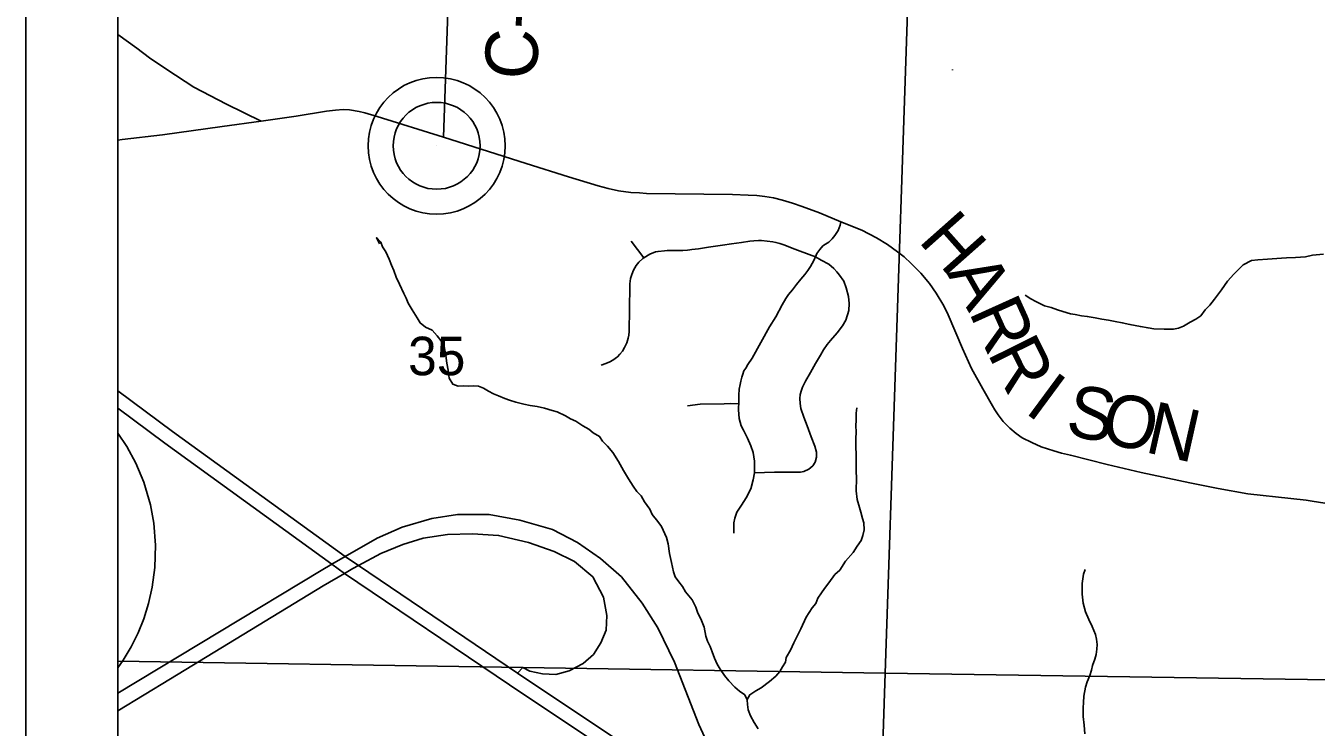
# Model space of a CAD drawing. Extents: x 0 to 34, y 0 to 22.
# Drawn here: x 2 to 3.401, y 17.753 to 18.515 of the extents above; entities that cross this region are included whole.
import ezdxf

# ---------------------------------------------------------------- set-up
doc = ezdxf.new("R2010")
doc.units = 0
for name, color, linetype in [('Default', 7, 'Continuous'), ('GM_X_County_Road', 7, 'Continuous'), ('GM_X_County_Road_Text', 7, 'Continuous'), ('GM_X_Interchange_Ramps', 7, 'Continuous'), ('GM_X_Interstate_Route', 7, 'Continuous'), ('GM_X_Minor_River', 7, 'Continuous'), ('GM_X_Section', 7, 'Continuous'), ('GM_X_Section_Text', 7, 'Continuous'), ('GM_X_State_Route', 7, 'Continuous'), ('GM_X_Township_Road', 7, 'Continuous'), ('GM_X_Unincorporated', 7, 'Continuous'), ('GM_X_Unincorporated_Location', 7, 'Continuous'), ('GM_X_US_Route', 7, 'Continuous'), ('SH_Data', 7, 'Continuous')]:
    doc.layers.add(name, color=color, linetype=linetype)

msp = doc.modelspace()

# ---------------------------------------------------------------- linework, layer by layer
at = {"layer": 'Default'}
for points in [[(2.1, 18.8179), (2.1, 17.8244), (2.9334, 17.8114), (2.9671, 18.8096)], [(2.1, 17.8244), (2.1, 16.8301), (2.9007, 16.8204), (2.9334, 17.8114)]]:
    msp.add_lwpolyline(points, close=True, dxfattribs=at)
at = {"layer": 'GM_X_County_Road'}
for points in [[(2.4536, 18.3939), (2.4734, 18.9711), (2.4789, 19.2126), (2.4779, 19.2343), (2.4729, 19.258), (2.466, 19.2847), (2.4564, 19.3082), (2.4379, 19.3402), (2.4089, 19.3759), (2.4042, 19.3829), (2.4024, 19.3879), (2.4033, 19.3939), (2.5108, 19.6061), (2.522, 19.6255), (2.5381, 19.646), (2.5504, 19.6643), (2.5583, 19.6763), (2.5688, 19.6992), (2.5863, 19.7508)], [(2.1, 18.5055), (2.1205, 18.4907), (2.1344, 18.4804), (2.1533, 18.4675), (2.1824, 18.4485), (2.218, 18.4299), (2.2556, 18.4113)], [(2.1, 18.3907), (2.1045, 18.3913), (2.1483, 18.3966), (2.2132, 18.4055), (2.2556, 18.4113), (2.2937, 18.4169), (2.3266, 18.4222), (2.3362, 18.4235), (2.3446, 18.4239), (2.3514, 18.4237), (2.362, 18.4218), (2.3681, 18.4204), (2.3817, 18.4164), (2.4536, 18.3939), (2.5435, 18.3655), (2.5893, 18.351), (2.6215, 18.341), (2.6326, 18.3381), (2.6437, 18.3358), (2.6571, 18.334), (2.6665, 18.3333), (2.6742, 18.3329), (2.7675, 18.3316), (2.7844, 18.331), (2.794, 18.3304), (2.8027, 18.3295), (2.812, 18.328), (2.822, 18.3256), (2.8326, 18.3224), (2.8433, 18.3186), (2.8621, 18.3116), (2.8851, 18.3021), (2.9081, 18.2929), (2.9238, 18.2847), (2.9358, 18.2774), (2.9469, 18.2694), (2.9538, 18.2638), (2.9617, 18.2568), (2.9722, 18.2462), (2.9815, 18.2349), (2.9888, 18.2245), (2.9969, 18.2106), (3.0017, 18.2007), (3.0172, 18.1641), (3.0271, 18.1424), (3.0395, 18.1205), (3.0499, 18.102), (3.0526, 18.0975), (3.0561, 18.092), (3.0616, 18.085), (3.0687, 18.0775), (3.0757, 18.0717), (3.0823, 18.0673), (3.0928, 18.0619), (3.1028, 18.0575), (3.1164, 18.0531), (3.125, 18.0505), (3.1345, 18.0481), (3.1746, 18.0383), (3.2114, 18.0294), (3.2643, 18.0182), (3.2951, 18.012), (3.3271, 18.0064), (3.3739, 18.0011), (3.3905, 17.9992), (3.3972, 17.9982)], [(3.3972, 17.9982), (3.4107, 17.9962)]]:
    msp.add_lwpolyline(points, dxfattribs=at)
at = {"layer": 'GM_X_Interchange_Ramps'}
for points in [[(2.1, 18.0723), (2.1098, 18.0577), (2.1195, 18.0397), (2.1281, 18.0191), (2.1355, 17.9942), (2.1391, 17.9744), (2.141, 17.9506), (2.1403, 17.9262), (2.1374, 17.9048), (2.1334, 17.8869), (2.1282, 17.8704), (2.122, 17.8552), (2.1145, 17.8399), (2.1058, 17.8253), (2.1, 17.8169)], [(2.1, 17.7703), (2.157, 17.8051), (2.323, 17.9061), (2.3462, 17.9197), (2.3553, 17.9251), (2.3612, 17.9283), (2.3857, 17.9414), (2.4094, 17.951), (2.4317, 17.9581), (2.4581, 17.962), (2.485, 17.9628), (2.5135, 17.9611), (2.546, 17.9533), (2.574, 17.9435), (2.5959, 17.9325), (2.616, 17.916), (2.6275, 17.8939), (2.631, 17.8741), (2.6302, 17.8579), (2.6246, 17.8441), (2.6166, 17.8316), (2.6054, 17.8219), (2.5903, 17.8138), (2.5757, 17.81), (2.5613, 17.8107), (2.5474, 17.8134), (2.5397, 17.8175), (2.5339, 17.8113)]]:
    msp.add_lwpolyline(points, dxfattribs=at)
at = {"layer": 'GM_X_Interstate_Route'}
for points in [[(2.1, 18.1183), (2.1593, 18.0739), (2.3469, 17.9381), (2.3612, 17.9283), (2.5339, 17.8113), (2.7627, 17.6585), (2.8343, 17.6093), (3.4225, 17.2149)], [(2.1, 18.0994), (2.1509, 18.0613), (2.3324, 17.9297), (2.3462, 17.9197), (2.5255, 17.7987), (2.7293, 17.6625)], [(2.1, 17.7894), (2.3209, 17.923), (2.3324, 17.9297), (2.3469, 17.9381), (2.3815, 17.9581), (2.4088, 17.9699), (2.4408, 17.9795), (2.4687, 17.9836), (2.5031, 17.9836), (2.5364, 17.9777), (2.572, 17.9676), (2.5993, 17.9533), (2.6242, 17.9361), (2.6468, 17.9159), (2.6693, 17.8874), (2.6866, 17.8607), (2.7044, 17.8233), (2.7311, 17.7556), (2.7465, 17.7217)]]:
    msp.add_lwpolyline(points, dxfattribs=at)
at = {"layer": 'GM_X_Minor_River'}
for points in [[(3.0064, 18.4669), (3.0063, 18.4674)], [(2.781, 17.7876), (2.775, 17.7916), (2.7699, 17.7959), (2.7637, 17.803), (2.7589, 17.8089), (2.7542, 17.8155), (2.751, 17.8209), (2.7478, 17.8275), (2.7454, 17.8344), (2.7433, 17.8402), (2.7405, 17.846), (2.7387, 17.8514), (2.7368, 17.8613), (2.7337, 17.8687), (2.7294, 17.8775), (2.7277, 17.8829), (2.7238, 17.891), (2.7165, 17.8996), (2.7133, 17.9055), (2.7093, 17.9105), (2.7053, 17.916), (2.7036, 17.9214), (2.7013, 17.9317), (2.699, 17.9413), (2.6978, 17.952), (2.6958, 17.9589), (2.6905, 17.9709), (2.6865, 17.9763), (2.6803, 17.9838), (2.6778, 17.9895), (2.6721, 17.9977), (2.6685, 18.0039), (2.6637, 18.0087), (2.6597, 18.0145), (2.6547, 18.0226), (2.6493, 18.0316), (2.6436, 18.0413), (2.6374, 18.051), (2.6316, 18.058), (2.6265, 18.0635), (2.6232, 18.0686), (2.6162, 18.0726), (2.6114, 18.0766), (2.605, 18.0802), (2.5972, 18.0851), (2.5916, 18.0879), (2.5861, 18.0912), (2.5771, 18.0953), (2.5715, 18.097), (2.5632, 18.0995), (2.5553, 18.1013), (2.5477, 18.1024), (2.5409, 18.1037), (2.5323, 18.1059), (2.5255, 18.1081), (2.5203, 18.1098), (2.5135, 18.1127), (2.5079, 18.1151), (2.5027, 18.118), (2.4971, 18.1212), (2.4915, 18.1233), (2.4858, 18.1235), (2.4809, 18.1233), (2.4759, 18.1235), (2.4695, 18.1233), (2.4639, 18.1254), (2.4599, 18.132), (2.4587, 18.1408), (2.4571, 18.1484), (2.4562, 18.1565), (2.4543, 18.1664), (2.4507, 18.173), (2.4467, 18.1781), (2.4412, 18.1843), (2.4341, 18.1876), (2.4282, 18.192), (2.425, 18.1974), (2.4196, 18.2064), (2.4153, 18.2137), (2.4132, 18.2188), (2.4107, 18.2242), (2.4057, 18.2342), (2.4022, 18.2419), (2.3998, 18.2489), (2.397, 18.255), (2.3945, 18.2612), (2.391, 18.2693), (2.3874, 18.2748), (2.3857, 18.2798), (2.3809, 18.2849), (2.3841, 18.2779)], [(3.4095, 18.2667), (3.3974, 18.2656), (3.3897, 18.264), (3.3791, 18.2632), (3.3692, 18.2628), (3.3638, 18.2626), (3.3486, 18.2612), (3.338, 18.2608), (3.3311, 18.2599), (3.3222, 18.2553), (3.312, 18.245), (3.3053, 18.2373), (3.2985, 18.228), (3.2909, 18.218), (3.2858, 18.2113), (3.281, 18.2062), (3.2763, 18.1999), (3.2708, 18.1963), (3.2646, 18.1927), (3.2573, 18.1884), (3.2519, 18.1863), (3.2465, 18.1853), (3.2363, 18.1853), (3.2253, 18.1857), (3.2188, 18.1867), (3.2105, 18.1881), (3.2049, 18.1891), (3.1992, 18.1904), (3.1909, 18.1922), (3.183, 18.1936), (3.1759, 18.195), (3.1687, 18.196), (3.1615, 18.1974), (3.1528, 18.1992), (3.1464, 18.1998), (3.1396, 18.2012), (3.1347, 18.2021), (3.1264, 18.2043), (3.1204, 18.2064), (3.1137, 18.2089), (3.1065, 18.2107), (3.0968, 18.2152), (3.0916, 18.2181), (3.0853, 18.2221)], [(2.7833, 17.7825), (2.7863, 17.7878), (2.7929, 17.7921), (2.7987, 17.7953), (2.8077, 17.8022), (2.8147, 17.8081), (2.8191, 17.8132), (2.8219, 17.8181), (2.8251, 17.8233), (2.8257, 17.8282), (2.8305, 17.8364), (2.8342, 17.8443), (2.837, 17.8499), (2.8419, 17.8596), (2.8477, 17.8723), (2.8541, 17.8823), (2.8581, 17.8871), (2.8602, 17.8928), (2.8642, 17.8987), (2.8674, 17.9035), (2.8721, 17.9095), (2.8785, 17.9184), (2.884, 17.9231), (2.8904, 17.9332), (2.8987, 17.9424), (2.9031, 17.9494), (2.9071, 17.9554), (2.9092, 17.961), (2.9106, 17.967), (2.9101, 17.9747), (2.9087, 17.9796), (2.907, 17.9862), (2.9053, 17.9912), (2.903, 18), (2.9018, 18.0095), (2.9023, 18.0232), (2.9018, 18.0308), (2.9017, 18.0415), (2.9017, 18.0498), (2.9015, 18.0567), (2.9014, 18.0658), (2.9017, 18.0741), (2.9015, 18.0798), (2.9018, 18.0867), (2.902, 18.0939), (2.9027, 18.0999)], [(3.1496, 17.7547), (3.1484, 17.7642), (3.1484, 17.7737), (3.1486, 17.7794), (3.1492, 17.7862), (3.151, 17.7961), (3.1528, 17.8017), (3.1557, 17.8088), (3.1574, 17.8145), (3.1587, 17.8197), (3.1612, 17.8265), (3.1625, 17.8314), (3.1631, 17.8374), (3.1637, 17.8424), (3.1627, 17.8481), (3.1618, 17.8534), (3.1583, 17.8619), (3.1544, 17.8697), (3.1508, 17.8778), (3.1485, 17.8874), (3.1473, 17.8973), (3.1473, 17.9087), (3.1488, 17.9189), (3.1505, 17.9238)], [(2.7953, 17.7506), (2.7909, 17.7576), (2.787, 17.765), (2.7846, 17.7715), (2.784, 17.7772), (2.7834, 17.7822), (2.781, 17.7876)], [(3.1501, 17.7455), (3.1496, 17.7547)]]:
    msp.add_lwpolyline(points, dxfattribs=at)
at = {"layer": 'GM_X_Section'}
for points in [[(2.9671, 18.8096), (3.9584, 18.8022), (3.923, 17.7965), (2.9334, 17.8114)], [(3.923, 17.7965), (3.9054, 16.8066), (2.9007, 16.8204), (2.9334, 17.8114)]]:
    msp.add_lwpolyline(points, close=True, dxfattribs=at)
at = {"layer": 'GM_X_State_Route'}
msp.add_lwpolyline([(2.1, 19.8108), (2.1, 16.7408)], dxfattribs=at)
at = {"layer": 'GM_X_Township_Road'}
msp.add_line((2.6712, 18.2628), (2.6575, 18.2809), dxfattribs=at)
for points in [[(2.769, 17.9634), (2.7688, 17.9672), (2.769, 17.9748), (2.7702, 17.9797), (2.7724, 17.9864), (2.7772, 17.994), (2.7825, 18.002), (2.7875, 18.0118), (2.7899, 18.0216), (2.7914, 18.029), (2.7915, 18.0417), (2.79, 18.0513), (2.7874, 18.0586), (2.784, 18.0666), (2.7793, 18.0756), (2.7769, 18.0803), (2.7746, 18.0881), (2.7742, 18.0974), (2.7741, 18.1006), (2.7744, 18.1042), (2.7745, 18.1134), (2.7748, 18.1199), (2.7757, 18.1251), (2.7764, 18.1287), (2.7777, 18.1329), (2.7786, 18.1362), (2.7799, 18.1398), (2.7821, 18.143), (2.7841, 18.1467), (2.7888, 18.1539), (2.8078, 18.1877), (2.8146, 18.1987), (2.8214, 18.2118), (2.8256, 18.2185), (2.8285, 18.2229), (2.8326, 18.228), (2.8371, 18.2338), (2.8419, 18.2395), (2.8462, 18.2448), (2.8492, 18.249), (2.8523, 18.2535), (2.8542, 18.2567), (2.8557, 18.2598), (2.8571, 18.2623), (2.8575, 18.2638), (2.8593, 18.2674), (2.8625, 18.2718), (2.8656, 18.2758), (2.8685, 18.2777), (2.872, 18.2799), (2.8758, 18.2834), (2.8787, 18.2872), (2.8809, 18.2903), (2.8824, 18.2927), (2.8834, 18.2955), (2.8846, 18.2985), (2.8851, 18.3021)], [(2.6248, 18.1463), (2.6299, 18.1478), (2.6342, 18.1497), (2.6376, 18.1516), (2.6427, 18.1552), (2.645, 18.1579), (2.6479, 18.1613), (2.6504, 18.1653), (2.6527, 18.1704), (2.6542, 18.1753), (2.6548, 18.1787), (2.6552, 18.1827), (2.6561, 18.2319), (2.6562, 18.2345), (2.6568, 18.2403), (2.6581, 18.2448), (2.66, 18.2495), (2.6629, 18.2544), (2.6659, 18.2581), (2.6703, 18.2622), (2.6712, 18.2628), (2.6779, 18.2669), (2.684, 18.2692), (2.6867, 18.2698), (2.6937, 18.2705), (2.6966, 18.2706), (2.7027, 18.2708), (2.7084, 18.2709), (2.7135, 18.2708), (2.7186, 18.2712), (2.7213, 18.2715), (2.7235, 18.2718), (2.7307, 18.2727), (2.7414, 18.2743), (2.7566, 18.2765), (2.7665, 18.278), (2.7773, 18.2796), (2.7863, 18.2808), (2.7908, 18.2813), (2.7958, 18.2816), (2.7991, 18.2816), (2.8051, 18.2811), (2.8113, 18.2803), (2.8147, 18.2796), (2.8188, 18.2783), (2.8243, 18.2765), (2.8323, 18.2733), (2.8409, 18.27), (2.8575, 18.2638), (2.8639, 18.2603), (2.8722, 18.2558), (2.8775, 18.2512), (2.8808, 18.2477), (2.8839, 18.2441), (2.8886, 18.2374), (2.8911, 18.2302), (2.8935, 18.2209), (2.8944, 18.2132), (2.8939, 18.2054), (2.8906, 18.1949), (2.8871, 18.1887), (2.8811, 18.1813), (2.8741, 18.173), (2.8704, 18.1686), (2.8664, 18.1628), (2.8631, 18.157), (2.8578, 18.1478), (2.8521, 18.138), (2.8468, 18.1289), (2.8434, 18.1221), (2.8423, 18.1189), (2.8412, 18.1141), (2.8408, 18.1098), (2.841, 18.1043), (2.8418, 18.0991), (2.8451, 18.0895), (2.8486, 18.0801), (2.8531, 18.0681), (2.8569, 18.058), (2.8588, 18.0516), (2.8589, 18.046), (2.8572, 18.0405), (2.8546, 18.0366), (2.8506, 18.033), (2.8451, 18.0305), (2.8414, 18.0299), (2.8327, 18.0298), (2.8132, 18.0297), (2.7914, 18.029)], [(2.7186, 18.102), (2.7324, 18.1039), (2.7583, 18.1042), (2.7658, 18.1043), (2.7744, 18.1042)]]:
    msp.add_lwpolyline(points, dxfattribs=at)
at = {"layer": 'GM_X_Unincorporated'}
for radius in [0.0744, 0.0472]:
    msp.add_circle((2.4462, 18.3846), radius, dxfattribs=at)
at = {"layer": 'GM_X_Unincorporated_Location'}
msp.add_line((2.4462, 18.3846), (2.4462, 18.3846), dxfattribs=at)
at = {"layer": 'GM_X_US_Route'}
msp.add_lwpolyline([(2.1, 18.0994), (2.1509, 18.0613), (2.3324, 17.9297), (2.3462, 17.9197), (2.5255, 17.7987), (2.7293, 17.6625)], dxfattribs=at)
at = {"layer": 'SH_Data'}
for p, q in [((2, 21), (2, 14)), ((2.1, 20.9), (2.1, 14.1))]:
    msp.add_line(p, q, dxfattribs=at)

# ---------------------------------------------------------------- texts
at = {"layer": 'GM_X_County_Road_Text'}
for s, height, rotation, p in [('C-21', 0.05682, 87.9423, (2.5551, 18.4561)), ('H', 0.0568, 311.5766, (2.9683, 18.2811)), ('A', 0.0568, 299.6497, (2.9997, 18.2463)), ('R', 0.0568, 294.3059, (3.0238, 18.2041)), ('R', 0.0568, 296.4658, (3.044, 18.1594)), ('I', 0.0568, 323.5697, (3.0835, 18.0954)), ('S', 0.0568, 349.4089, (3.1277, 18.0705)), ('O', 0.0568, 346.7014, (3.1647, 18.0636)), ('N', 0.0568, 347.3367, (3.214, 18.0519))]:
    msp.add_text(s, height=height, rotation=rotation, dxfattribs=at).set_placement(p)
at = {"layer": 'GM_X_Section_Text'}
msp.add_text('35', height=0.04186, rotation=0, dxfattribs=at).set_placement((2.4152, 18.1352))

doc.saveas('drawing.dxf')
